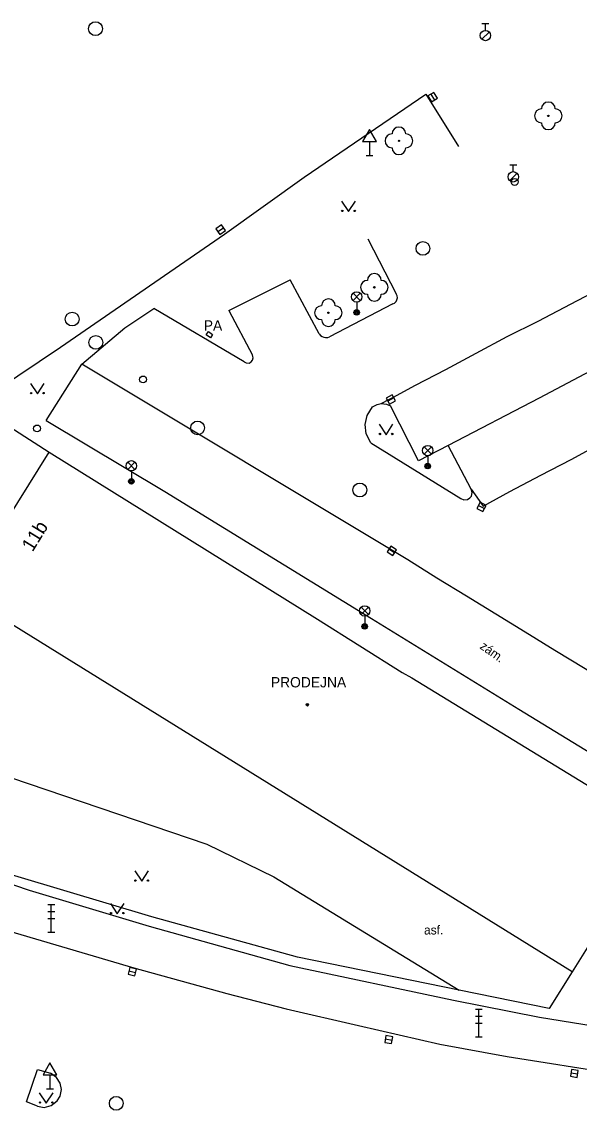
# Model space of a CAD drawing. Extents: x -598341 to -594502, y -1162301 to -1161406.
# Drawn here: x -598037.9 to -597997.5, y -1161485.4 to -1161406.4 of the extents above; entities that cross this region are included whole.
import ezdxf

# ---------------------------------------------------------------- set-up
doc = ezdxf.new("R2010")
doc.units = 0
for name, color, linetype in [('Vrstva 10', 7, 'Continuous'), ('Vrstva 11', 7, 'Continuous'), ('Vrstva 22', 7, 'Continuous'), ('Vrstva 27', 7, 'Continuous'), ('Vrstva 28', 7, 'Continuous'), ('Vrstva 33', 7, 'Continuous'), ('Vrstva 34', 7, 'Continuous'), ('Vrstva 36', 7, 'Continuous'), ('Vrstva 39', 7, 'Continuous'), ('Vrstva 40', 7, 'Continuous'), ('Vrstva 41', 7, 'Continuous'), ('Vrstva 46', 7, 'Continuous'), ('Vrstva 5', 7, 'Continuous'), ('Vrstva 7', 7, 'Continuous')]:
    doc.layers.add(name, color=color, linetype=linetype)

msp = doc.modelspace()

# ---------------------------------------------------------------- linework, layer by layer
at = {"layer": 'Vrstva 10'}
for points in [[(-598041.3, -1161434.19), (-598035.1, -1161430.03), (-598023.22, -1161421.84), (-598017.44, -1161417.72), (-598008.63, -1161411.7), (-598006.26, -1161415.48)], [(-598012.83, -1161422.19), (-598010.77, -1161426.17)], [(-598022.91, -1161427.39), (-598018.46, -1161425.15)], [(-598016.35, -1161429.06), (-598018.46, -1161425.15)], [(-598011.02, -1161426.9), (-598015.62, -1161429.29)], [(-598011.02, -1161426.9), (-598010.91, -1161426.84), (-598010.78, -1161426.72), (-598010.72, -1161426.6), (-598010.69, -1161426.46), (-598010.7, -1161426.32), (-598010.77, -1161426.17)], [(-598033.55, -1161431.26), (-598030.44, -1161428.63), (-598028.35, -1161427.23)], [(-598021.79, -1161431.1), (-598028.35, -1161427.23)], [(-598022.91, -1161427.39), (-598021.18, -1161430.61)], [(-598016.35, -1161429.06), (-598016.25, -1161429.19), (-598016.14, -1161429.26), (-598016.03, -1161429.31), (-598015.89, -1161429.34), (-598015.73, -1161429.33), (-598015.62, -1161429.29)], [(-598021.79, -1161431.1), (-598021.64, -1161431.18), (-598021.44, -1161431.19), (-598021.28, -1161431.11), (-598021.18, -1161430.99), (-598021.13, -1161430.81), (-598021.18, -1161430.61)], [(-598036.15, -1161435.36), (-598033.55, -1161431.26)], [(-598012.61, -1161436.96), (-598012.95, -1161436.32), (-598013.02, -1161435.64), (-598012.89, -1161434.98), (-598012.49, -1161434.37), (-598012.16, -1161434.19), (-598011.87, -1161434.13)], [(-598011.87, -1161434.13), (-598011.49, -1161434.17), (-598011.19, -1161434.3)], [(-598007.01, -1161437.17), (-598009.16, -1161438.27), (-598011.19, -1161434.3)], [(-598036.15, -1161435.36), (-598027.54, -1161440.49), (-598012.56, -1161449.7), (-598001.88, -1161456.27)], [(-598012.61, -1161436.96), (-598006.08, -1161441.01)], [(-598005.34, -1161440.34), (-598007.01, -1161437.17)], [(-598006.08, -1161441.01), (-598005.87, -1161441.1), (-598005.62, -1161441.08), (-598005.44, -1161440.97), (-598005.33, -1161440.84), (-598005.27, -1161440.58), (-598005.34, -1161440.34)], [(-598001.88, -1161456.27), (-597976.48, -1161471.82)], [(-598042.62, -1161471.27), (-598038.4, -1161472.49), (-598029.78, -1161475.02)], [(-598029.78, -1161475.02), (-598023.06, -1161476.88), (-598018.75, -1161478.01), (-598013.51, -1161479.22), (-598007.61, -1161480.57), (-598002.73, -1161481.46), (-597986.84, -1161483.98), (-597980.42, -1161484.83), (-597975.8, -1161485.33)], [(-598036.76, -1161485.06), (-598037.56, -1161484.73), (-598036.77, -1161482.4), (-598035.82, -1161482.66)], [(-598036.76, -1161485.06), (-598036.28, -1161485.14), (-598035.78, -1161485.01), (-598035.34, -1161484.67), (-598035.13, -1161484.32), (-598035.04, -1161483.85), (-598035.13, -1161483.38), (-598035.39, -1161482.97), (-598035.82, -1161482.66)]]:
    msp.add_lwpolyline(points, dxfattribs=at)
at = {"layer": 'Vrstva 11'}
for points in [[(-598011.87, -1161434.13), (-598011.25, -1161433.8), (-598011.03, -1161433.68), (-598009.38, -1161432.79), (-598007.17, -1161431.65), (-598004.97, -1161430.47), (-598002.74, -1161429.26), (-598000.48, -1161428.15), (-597997.63, -1161426.66), (-597994.8, -1161425.19), (-597992.54, -1161424.06), (-597990.35, -1161422.83), (-597988.13, -1161421.64), (-597985.91, -1161420.49), (-597983.3, -1161419.14), (-597980.7, -1161417.78), (-597978.47, -1161416.6), (-597976.26, -1161415.5), (-597974, -1161414.24)], [(-598005.34, -1161440.34), (-598004.48, -1161441.56), (-598002.53, -1161440.49), (-598000.3, -1161439.32), (-597998.1, -1161438.17), (-597995.93, -1161437), (-597993.01, -1161435.51), (-597990.2, -1161434.03), (-597987.97, -1161432.88), (-597985.76, -1161431.72), (-597983.52, -1161430.54), (-597981.31, -1161429.41), (-597978.68, -1161428.02), (-597976.06, -1161426.66), (-597973.83, -1161425.48), (-597971.62, -1161424.37), (-597969.26, -1161423.17)], [(-597973.81, -1161467.71), (-597984.3, -1161461.22), (-597986.42, -1161459.91), (-597988.56, -1161458.58), (-597990.71, -1161457.3), (-597992.85, -1161455.96), (-597994.97, -1161454.66), (-597997.09, -1161453.35), (-597999.27, -1161452.02), (-598001.43, -1161450.69), (-598003.55, -1161449.39), (-598005.67, -1161448.08), (-598007.82, -1161446.79), (-598009.93, -1161445.45), (-598033.55, -1161431.26)], [(-597996.31, -1161431.56), (-598000.42, -1161433.74), (-598007.01, -1161437.17)], [(-598041.3, -1161434.19), (-598035.92, -1161437.64)], [(-598050.09, -1161460.14), (-598042.57, -1161464.84), (-598040.04, -1161460.8), (-598024.51, -1161466.06), (-598019.65, -1161468.42), (-598006.22, -1161476.65)], [(-598049.17, -1161465.38), (-598037.38, -1161469.39), (-598028.69, -1161472.01), (-598018.49, -1161474.85), (-598006.63, -1161477.36), (-598000.39, -1161478.6), (-597986.34, -1161480.88)]]:
    msp.add_lwpolyline(points, dxfattribs=at)
msp.add_lwpolyline([(-598024.39, -1161428.91), (-598024.08, -1161429.11), (-598024.24, -1161429.35), (-598024.55, -1161429.14)], close=True, dxfattribs=at)
at = {"layer": 'Vrstva 22'}
for centre in [(-597999.75, -1161413.27), (-598010.58, -1161415.08), (-598012.36, -1161425.7), (-598015.69, -1161427.54)]:
    msp.add_circle(centre, 0.05, dxfattribs=at)
for centre, start, end in [((-597999.75, -1161412.77), 0, 180), ((-598000.25, -1161413.27), 90, 270), ((-597999.25, -1161413.27), 270, 90), ((-598010.58, -1161414.58), 0, 180), ((-597999.75, -1161413.77), 180, 0), ((-598011.08, -1161415.08), 90, 270), ((-598010.08, -1161415.08), 270, 90), ((-598010.58, -1161415.58), 180, 0), ((-598012.86, -1161425.7), 90, 270), ((-598012.36, -1161425.2), 0, 180), ((-598011.86, -1161425.7), 270, 90), ((-598015.69, -1161427.04), 0, 180), ((-598012.36, -1161426.2), 180, 0), ((-598016.19, -1161427.54), 90, 270), ((-598015.19, -1161427.54), 270, 90), ((-598015.69, -1161428.04), 180, 0)]:
    msp.add_arc(centre, 0.5, start, end, dxfattribs=at)
at = {"layer": 'Vrstva 27'}
for p, q in [((-598008.26, -1161411.696), (-598008, -1161412.124)), ((-598023.705, -1161421.663), (-598023.295, -1161421.377)), ((-598010.943, -1161433.716), (-598011.377, -1161433.963)), ((-598004.811, -1161441.503), (-598004.369, -1161441.737)), ((-598011.299, -1161444.662), (-598010.881, -1161444.938)), ((-598030.142, -1161475.247), (-598029.658, -1161475.373)), ((-598011.566, -1161480.185), (-598011.074, -1161480.276)), ((-597998.117, -1161482.64), (-597997.623, -1161482.719))]:
    msp.add_line(p, q, dxfattribs=at)
for points in [[(-598008.473, -1161411.826), (-598008.214, -1161412.253), (-598007.787, -1161411.994), (-598008.046, -1161411.567)], [(-598023.562, -1161421.868), (-598023.152, -1161421.582), (-598023.438, -1161421.172), (-598023.848, -1161421.458)], [(-598011.067, -1161433.498), (-598011.502, -1161433.746), (-598011.254, -1161434.181), (-598010.819, -1161433.933)], [(-598004.928, -1161441.724), (-598004.486, -1161441.958), (-598004.252, -1161441.516), (-598004.694, -1161441.282)], [(-598011.436, -1161444.871), (-598011.019, -1161445.146), (-598010.744, -1161444.729), (-598011.161, -1161444.454)], [(-598030.205, -1161475.489), (-598029.721, -1161475.615), (-598029.595, -1161475.132), (-598030.079, -1161475.005)], [(-598011.611, -1161480.43), (-598011.12, -1161480.522), (-598011.028, -1161480.03), (-598011.52, -1161479.939)], [(-597998.156, -1161482.887), (-597997.662, -1161482.966), (-597997.584, -1161482.472), (-597998.077, -1161482.394)]]:
    msp.add_lwpolyline(points, close=True, dxfattribs=at)
for centre in [(-598032.57, -1161406.95), (-598008.84, -1161422.88), (-598034.26, -1161428), (-598032.54, -1161429.69), (-598025.17, -1161435.89), (-598013.41, -1161440.39), (-598031.06, -1161484.85)]:
    msp.add_circle(centre, 0.5, dxfattribs=at)
at = {"layer": 'Vrstva 28'}
for p, q in [((-598004.568, -1161407.722), (-598004.038, -1161407.192)), ((-598004.56, -1161406.575), (-598004.06, -1161406.575)), ((-598004.31, -1161407.075), (-598004.31, -1161406.575)), ((-598002.548, -1161417.962), (-598002.018, -1161417.432)), ((-598002.54, -1161416.815), (-598002.04, -1161416.815)), ((-598002.29, -1161417.315), (-598002.29, -1161416.815))]:
    msp.add_line(p, q, dxfattribs=at)
for centre, radius in [((-598004.31, -1161407.45), 0.375), ((-598002.29, -1161417.69), 0.375), ((-598002.19, -1161418.06), 0.25), ((-598029.12, -1161432.38), 0.25), ((-598036.8, -1161435.93), 0.25)]:
    msp.add_circle(centre, radius, dxfattribs=at)
at = {"layer": 'Vrstva 33'}
for p, q in [((-598013.905, -1161426.66), (-598013.375, -1161426.13)), ((-598013.905, -1161426.13), (-598013.375, -1161426.66)), ((-598013.64, -1161426.77), (-598013.64, -1161427.52)), ((-598008.755, -1161437.8), (-598008.225, -1161437.27)), ((-598008.755, -1161437.27), (-598008.225, -1161437.8)), ((-598008.49, -1161437.91), (-598008.49, -1161438.66)), ((-598030.235, -1161438.9), (-598029.705, -1161438.37)), ((-598030.235, -1161438.37), (-598029.705, -1161438.9)), ((-598029.97, -1161439.01), (-598029.97, -1161439.76)), ((-598013.325, -1161449.42), (-598012.795, -1161448.89)), ((-598013.325, -1161448.89), (-598012.795, -1161449.42)), ((-598013.06, -1161449.53), (-598013.06, -1161450.28)), ((-598036.02, -1161470.44), (-598035.52, -1161470.44)), ((-598036.02, -1161470.94), (-598035.52, -1161470.94)), ((-598035.77, -1161472.44), (-598035.77, -1161470.44)), ((-598036.02, -1161471.44), (-598035.52, -1161471.44)), ((-598036.02, -1161472.44), (-598035.52, -1161472.44)), ((-598005.04, -1161478.03), (-598004.54, -1161478.03)), ((-598004.79, -1161480.03), (-598004.79, -1161478.03)), ((-598005.04, -1161478.53), (-598004.54, -1161478.53)), ((-598005.04, -1161479.03), (-598004.54, -1161479.03)), ((-598005.04, -1161480.03), (-598004.54, -1161480.03))]:
    msp.add_line(p, q, dxfattribs=at)
for centre, radius in [((-598013.64, -1161426.395), 0.375), ((-598013.64, -1161427.52), 0.2), ((-598013.64, -1161427.52), 0.145), ((-598013.64, -1161427.52), 0.0876), ((-598008.49, -1161437.535), 0.375), ((-598029.97, -1161438.635), 0.375), ((-598008.49, -1161438.66), 0.2), ((-598008.49, -1161438.66), 0.145), ((-598008.49, -1161438.66), 0.0876), ((-598029.97, -1161439.76), 0.2), ((-598029.97, -1161439.76), 0.145), ((-598029.97, -1161439.76), 0.0876), ((-598013.06, -1161449.155), 0.375), ((-598013.06, -1161450.28), 0.2), ((-598013.06, -1161450.28), 0.145), ((-598013.06, -1161450.28), 0.0876)]:
    msp.add_circle(centre, radius, dxfattribs=at)
at = {"layer": 'Vrstva 34'}
for p, q in [((-598012.71, -1161415.132), (-598012.71, -1161416.15)), ((-598012.96, -1161416.15), (-598012.46, -1161416.15)), ((-598035.87, -1161482.782), (-598035.87, -1161483.8)), ((-598036.12, -1161483.8), (-598035.62, -1161483.8))]:
    msp.add_line(p, q, dxfattribs=at)
for points in [[(-598013.21, -1161415.132), (-598012.21, -1161415.132), (-598012.71, -1161414.266)], [(-598036.37, -1161482.782), (-598035.37, -1161482.782), (-598035.87, -1161481.916)]]:
    msp.add_lwpolyline(points, close=True, dxfattribs=at)
at = {"layer": 'Vrstva 36'}
for points in [[(-598014.73, -1161419.46), (-598014.23, -1161420.21), (-598013.73, -1161419.46)], [(-598037.28, -1161432.67), (-598036.78, -1161433.42), (-598036.28, -1161432.67)], [(-598012.01, -1161435.63), (-598011.51, -1161436.38), (-598011.01, -1161435.63)], [(-598029.72, -1161468), (-598029.22, -1161468.75), (-598028.72, -1161468)], [(-598031.49, -1161470.36), (-598030.99, -1161471.11), (-598030.49, -1161470.36)], [(-598036.64, -1161484.09), (-598036.14, -1161484.84), (-598035.64, -1161484.09)]]:
    msp.add_lwpolyline(points, dxfattribs=at)
for centre in [(-598014.68, -1161420.16), (-598013.781, -1161420.16), (-598037.23, -1161433.37), (-598036.331, -1161433.37), (-598011.96, -1161436.33), (-598011.061, -1161436.33), (-598029.67, -1161468.7), (-598028.771, -1161468.7), (-598031.44, -1161471.06), (-598030.541, -1161471.06), (-598036.59, -1161484.79), (-598035.691, -1161484.79)]:
    msp.add_circle(centre, 0.05, dxfattribs=at)
at = {"layer": 'Vrstva 39'}
for radius in [0.09, 0.0398]:
    msp.add_circle((-598017.21, -1161455.96), radius, dxfattribs=at)
at = {"layer": 'Vrstva 5'}
for p, q in [((-598042.31, -1161447.86), (-598035.92, -1161437.64)), ((-598035.92, -1161437.64), (-598016.47, -1161449.75)), ((-597998.03, -1161475.32), (-598042.06, -1161448.02)), ((-598016.47, -1161449.75), (-598010.35, -1161453.61)), ((-598010.35, -1161453.61), (-598009.64, -1161454)), ((-598009.64, -1161454), (-597991.64, -1161465.03)), ((-597991.64, -1161465.03), (-597998.03, -1161475.32))]:
    msp.add_line(p, q, dxfattribs=at)
at = {"layer": 'Vrstva 7'}
for points in [[(-598006.22, -1161476.65), (-598017.93, -1161474.26), (-598028.49, -1161471.34), (-598047.65, -1161465.6), (-598050.16, -1161463.82)], [(-597998.03, -1161475.32), (-597999.69, -1161477.97), (-598006.22, -1161476.65)]]:
    msp.add_lwpolyline(points, dxfattribs=at)

# ---------------------------------------------------------------- texts
at = {"layer": 'Vrstva 40'}
msp.add_text('zám.', height=0.65, rotation=324.68639, dxfattribs=at).set_placement((-598004.77, -1161451.84))
msp.add_text('asf.', height=0.65, dxfattribs=at).set_placement((-598008.76, -1161472.61))
at = {"layer": 'Vrstva 41'}
for s, p in [('PA', (-598024.72, -1161428.84)), ('PRODEJNA', (-598019.86, -1161454.7))]:
    msp.add_text(s, height=0.75, dxfattribs=at).set_placement(p)
at = {"layer": 'Vrstva 46'}
msp.add_text('11b', height=1, rotation=58.31, dxfattribs=at).set_placement((-598037.13, -1161444.93))

doc.saveas('drawing.dxf')
